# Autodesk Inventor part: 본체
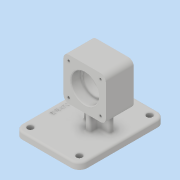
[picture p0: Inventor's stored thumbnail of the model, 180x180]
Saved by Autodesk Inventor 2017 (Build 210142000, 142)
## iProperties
Part Number: 본체
Material: 일반
Document SubType Name: Modeling
Designer: mrc
Density: 1 g/cm^3
Appearance: 기본값
Mass: 253.042 g
Surface Area: 542.794 cm^2
Volume: 253.042 cm^3
Author: mrc
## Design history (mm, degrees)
sketch "스케치2"
  geometry: L1 (-32, -32)-(32, -32); L2 (32, -32)-(32, 32); L3 (32, 32)-(-32, 32); L4 (-32, 32)-(-32, -32); L5 (-32, -32)-(32, 32); L6 (32, -32)-(-32, 32); 1 further point
  constraints: 12 end point, 2 midpoint, 2 parallel, 1 horizontal, 1 perpendicular
  dimensions: "d6" = 64 distance of L3.end L2.end; "d7" = 64 distance of L2.end L1.end
extrude "돌출2" new body sketch "스케치2" distance "d8" = 42; taper "d9" = 0 deg
node "작업 평면5"
  node "작업 평면4"
sketch "스케치4"
  geometry: L1 (68, -86)-(-30, -86); L2 (-30, -86)-(-30, 44); L3 (-30, 44)-(68, 44); L4 (68, 44)-(68, -86); L5 (68, -86)-(-30, 44); L6 (-30, -86)-(68, 44); L7 (64, 0)-(0, 0) reference; L8 (0, 0)-(0, -42) reference; L9 (64, -42)-(0, -42) reference; L10 (64, 0)-(64, -42) reference; L11 (0, -42)-(64, 0); 4 further points
  constraints: 14 end point, 4 midpoint, 2 parallel, 1 horizontal, 1 horizontal alignment, 1 perpendicular
  dimensions: "d17" = 62 distance from line of L2 point (32, -21); "d18" = 130 distance of L1.end L2.end; "d19" = 98 distance of L2.end L3.end
extrude "돌출3" join sketch "스케치4" distance "d20" = 10; taper "d21" = 0 deg
sketch "스케치5"
  geometry: L1 (64, 0)-(0, 0) reference; L2 (0, 0)-(0, -42) reference; L3 (64, -42)-(0, -42) reference; L4 (64, 0)-(64, -42) reference; L5 (36, -4)-(28, -4); L6 (28, -4)-(28, -38); L7 (28, -38)-(36, -38); L8 (36, -38)-(36, -4); L9 (36, -4)-(28, -38); L10 (28, -4)-(36, -38); L11 (52, -17)-(12, -17); L12 (12, -17)-(12, -25); L13 (12, -25)-(52, -25); L14 (52, -25)-(52, -17); L15 (52, -17)-(12, -25); L16 (12, -17)-(52, -25); L17 (-30, -86)-(-30, 44) reference; L18 (-30, 44)-(68, 44) reference; 3 further points
  constraints: 24 end point, 5 midpoint, 4 parallel, 2 horizontal, 2 perpendicular
  dimensions: "d22" = 62 distance from line of point (32, -21) L17; "d23" = 65 distance from line of L18 point (32, -21); "d24" = 8 distance of L11.end L12.end; "d25" = 8 distance of L5.start L5.end; "d26" = 40 distance of L11.start L11.end; "d27" = 34 distance of L5.end L6.end
extrude "돌출4" join sketch "스케치5" stored distance "d28" = 10; taper "d29" = 0 deg
sketch "스케치6"
  geometry: C1 r 18 at (0, 0); 1 further point
  constraints: 1 centre point, 1 coincident
  dimensions: "d30" = 36 diameter of C1
extrude "돌출5" cut sketch "스케치6" stored distance "d31" = 10; taper "d32" = 0 deg
sketch "스케치7"
  geometry: C1 r 21 at (0, 0); 1 further point
  constraints: 1 centre point, 1 coincident
  dimensions: "d33" = 42 diameter of C1
extrude "돌출6" cut sketch "스케치7" distance "d34" = 15; taper "d35" = 0 deg
sketch "스케치8"
  geometry: C1 r 21 at (0, 0); 1 further point
  constraints: 1 centre point, 1 coincident
  dimensions: "d36" = 42 diameter of C1
extrude "돌출7" cut sketch "스케치8" distance "d37" = 15; taper "d38" = 0 deg
sketch "스케치9"
  geometry: C1 r 18 at (0, 0) reference; 5 further points
  constraints: 2 horizontal alignment, 2 vertical alignment
  dimensions: "d39" = 48 distance of point (24, 24) point (-24, 24); "d40" = 48 distance of point (-24, -24) point (-24, 24); "d41" = 24 horizontal distance of point (0, 0) point (-24, 24); "d42" = 24 horizontal distance of point (0, 0) point (-24, -24)
hole "구멍1" sketch "스케치9" at (-24, 24), (24, 24), (24, -24), (-24, -24) diameter "d43" = 3.242; stored, may be unused: countersink angle "d47" = 90 deg, drill point angle "d49" = 118 deg; dims "d44" = 8, "d45" = 4, "d46" = 2, "d48" = 10
node "작업 평면6"
fillet "모깎기1" dims "d51" = 12
hole "구멍2" diameter "d54" = 9; stored, may be unused: countersink angle "d58" = 90 deg, drill point angle "d60" = 118 deg; dims "d52" = 10, "d53" = 10, "d55" = 8, "d56" = 4, "d57" = 2, "d59" = 20
hole "구멍3" diameter "d63" = 9; stored, may be unused: countersink angle "d67" = 90 deg, drill point angle "d69" = 118 deg; dims "d61" = 10, "d62" = 10, "d64" = 8, "d65" = 4, "d66" = 2, "d68" = 20
hole "구멍4" diameter "d72" = 9; stored, may be unused: countersink angle "d76" = 90 deg, drill point angle "d78" = 118 deg; dims "d70" = 10, "d71" = 10, "d73" = 8, "d74" = 4, "d75" = 2, "d77" = 20
hole "구멍5" diameter "d81" = 9; stored, may be unused: countersink angle "d85" = 90 deg, drill point angle "d87" = 118 deg; dims "d79" = 10, "d80" = 10, "d82" = 8, "d83" = 4, "d84" = 2, "d86" = 20
fillet "모깎기2" dims "d88" = 3
fillet "모깎기3" dims "d89" = 8
fillet "모깎기4" dims "d90" = 3
fillet "모깎기5" dims "d91" = 3
fillet "모깎기6" dims "d92" = 3
chamfer "모따기1" distance "d93" = 1; stored, may be unused: second distance "d94" = 2, angle "d95" = 45 deg
chamfer "모따기2" distance "d96" = 1; stored, may be unused: second distance "d97" = 2, angle "d98" = 45 deg
fillet "모깎기7" dims "d99" = 0.3
sketch "스케치12"
  geometry: L1 (-18, 41)-(56, 41) reference; L2 (-27, -74)-(-27, 32) reference; L3 (56, -83)-(-18, -83) reference; L4 (65, 32)-(65, -74) reference; L5 (15, -28)-(25, -28) reference; L6 (9, -20)-(9, -22) reference; L7 (25, -14)-(15, -14) reference; L8 (25, -7)-(25, -14) reference; L9 (33, -1)-(31, -1) reference; L10 (39, -14)-(39, -7) reference; L11 (49, -14)-(39, -14) reference; L12 (55, -22)-(55, -20) reference; L13 (39, -28)-(49, -28) reference; L14 (39, -35)-(39, -28) reference; L15 (31, -41)-(33, -41) reference; L16 (25, -28)-(25, -35) reference; L17 (-30, 32)-(-30, -74) reference; L18 (56, 44)-(-18, 44) reference; C1 r 4.5 at (-18, 32) reference; C2 r 4.5 at (-18, -74) reference; C3 r 4.5 at (56, -74) reference; C4 r 4.5 at (56, 32) reference; A1 r 9 centre (56, 32) between (65, 32) and (56, 41) reference; A2 r 9 centre (-18, 32) between (-18, 41) and (-27, 32) reference; A3 r 9 centre (-18, -74) between (-27, -74) and (-18, -83) reference; A4 r 9 centre (56, -74) between (56, -83) and (65, -74) reference; A5 r 6 centre (15, -22) between (9, -22) and (15, -28) reference; A6 r 6 centre (15, -20) between (15, -14) and (9, -20) reference; A7 r 6 centre (31, -7) between (31, -1) and (25, -7) reference; A8 r 6 centre (33, -7) between (39, -7) and (33, -1) reference; A9 r 6 centre (49, -20) between (55, -20) and (49, -14) reference; A10 r 6 centre (49, -22) between (49, -28) and (55, -22) reference; A11 r 6 centre (33, -35) between (33, -41) and (39, -35) reference; A12 r 6 centre (31, -35) between (25, -35) and (31, -41) reference; 2 further points
  constraints: 1 other
  dimensions: "d100" = 10 distance from line of point (-20, -21) L17; "d101" = 65 distance from line of point (-20, -21) L18
feature "엠보싱1" sketch "스케치12" dims "d6" = 64, "d7" = 64, "d19" = 98, "d102" = 0.5, "d103" = 0
node "솔리드2"
mirror "미러1"
node "투영된 루프1"
node "투영된 루프2"
node "투영된 루프3"
other parameters: "d11" = -32, "d50" = -21
